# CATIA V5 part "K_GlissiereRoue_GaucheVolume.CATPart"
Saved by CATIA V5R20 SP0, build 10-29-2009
Part number: glissiere_roue_gauche_volume
Publications: "Corps principal", "Corps principal1"
Bounding box of the stored display mesh (mm): x -74.995 to 74.995, y 360 to 515, z -25 to 24.995
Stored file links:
  G:\Khaled_CFAO_2011\ST2M\ST2M_GR1\cdurantin\cdurantin\Khaled\CAD_ThinkMOTION\K_GlissiereRoue_GaucheVolume.CATPart
  C:\Documents and Settings\cdurantin\Bureau\cdurantin\caddy.CATProduct
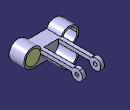
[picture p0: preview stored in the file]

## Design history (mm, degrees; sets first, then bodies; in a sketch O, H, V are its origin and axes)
External parameters (linked from other documents)
  `External.diamètre des barres` = 40 mm
  `External.Surepaisseur du tube` = 10 mm
  `External.largeur de la glissière` = 100 mm
  `External.Ecart entre les barres du corps` = 100 mm
  `External.Longueur de barres du corps` = 800 mm
Set1
  DatumSurface1: linked copy from another document
  Point1: linked copy from another document
  Point2: linked copy from another document
Body1 (main body)
  Sketch1 on face of DatumSurface1, origin (0, 400, 0), H (-1, 0, 0), V (0, 0, 1)
    circle A1 centre (-50, 0) radius 20
    reference projected point E2 (-50, 0) from Point1
    arc A2 centre (-50, 0) radius 25 from (-27.0871, 10) to (-50, -25) ccw
    circle A3 centre (50, 0) radius 20
    reference projected point E4 (50, 0) from Point2
    arc A4 centre (50, 0) radius 25 from (50, -25) to (27.0871, 10) ccw
    line L1 (-27.0871, 10) -> (27.0871, 10)
    reference projected point E5 (-50, 0) from Point1
    line L2 (-50, -25) -> (50, -25)
    reference projected point E6 (-50, 0) from Point1
    radius A1 = 20 {= `External.diamètre des barres` /2}
    radius A2 = 25 {= `External.diamètre des barres` /2+`External.Surepaisseur du tube` /2}
    radius A3 = 20 {= `External.diamètre des barres` /2}
    radius A4 = 25 {= `External.diamètre des barres` /2+`External.Surepaisseur du tube` /2}
    distance L1 E5 = 10 {= `External.Surepaisseur du tube`}
    distance L2 E6 = 25 {= `External.diamètre des barres` /2+`External.Surepaisseur du tube` /2}
    concentricity: E2 A1, A2 A1, E4 A3, A4 A3
    horizontal: L1 H
    tangency: L2 A4
  Pad1: profile Sketch1, direction (0, -1, 0), length 40 {= `External.diamètre des barres`}
  Sketch2 on start face of Pad1, origin (0, 400, 0), H (-1, 0, 0), V (0, 0, 1)
    arc A1 centre (0, 0) radius 20 from (-20, 0) to (20, 0) ccw
    point P1 (0, 0)
    reference projected point E1 (50, 0) from Point2
    reference projected point E2 (-50, 0) from Point1
    arc A2 centre (0, 0) radius 25 from (-25, 0) to (25, 0) ccw
    point P3 (20, 0)
    point P4 (25, 0)
    point P5 (-20, 0)
    point P6 (-25, 0)
    point P7 (-20, 0)
    point P8 (20, 0)
    point P9 (-25, 0)
    point P10 (25, 0)
    line L1 (20, 0) -> (25, 0)
    line L2 (-20, 0) -> (-25, 0)
    distance P1 E1 = 50 {= `External.Ecart entre les barres du corps` /2}
    distance P1 E2 = 50 {= `External.Ecart entre les barres du corps` /2}
    radius A1 = 20 {= `External.diamètre des barres` /2}
    radius A2 = 25 {= `External.diamètre des barres` /2+`External.Surepaisseur du tube` /2}
    concentricity: A2 A1
    coincidence: P3 A1, P3 H, P4 A2, P5 A1, P5 H, P6 A2, P3 P8, P4 P10, P5 P7, P6 P9
    horizontal: L1 H, L2 H
  Pad2: profile Sketch2, direction (0, 1, 0), length 50 {= `External.largeur de la glissière` -`External.diamètre des barres` -`External.Surepaisseur du tube`}
  Plane1: type Offset, RefPlane zx-plane, Offset 500 {= `External.Longueur de barres du corps` /2+`External.largeur de la glissière`}
  Sketch3 on Plane1, origin (0, 500, 0), H (-1, 0, 0), V (0, 0, 1)
    line L1 (-30, 15) -> (-20, 15)
    line L2 (-20, 15) -> (-20, 5)
    line L3 (-20, 5) -> (-30, 5)
    line L4 (-30, 5) -> (-30, 15)
    length L2 = 10 {= `External.Surepaisseur du tube`}
    length L1 = 10 {= `External.Surepaisseur du tube`}
    distance L3 H = 5 {= `External.Surepaisseur du tube` /2}
    distance L2 V = 20 {= `External.diamètre des barres` /2}
    horizontal: L1 H, L3 H
    vertical: L2 V, L4 V
  Shaft1: profile Sketch3, axis Sketch3.H, angle 360
  Sketch4 on start face of Pad1, origin (0, 400, 0), H (-1, 0, 0), V (0, 0, 1)
    line L1 (-20, 10) -> (-30, 10)
    line L2 (-30, 10) -> (-30, 0)
    line L3 (-30, 0) -> (-20, 0)
    line L4 (-20, 0) -> (-20, 10)
    length L4 = 10 {= `External.Surepaisseur du tube`}
    length L1 = 10 {= `External.Surepaisseur du tube`}
    distance L4 V = 20 {= `External.diamètre des barres` /2}
    distance L3 H = 0
    horizontal: L1 H, L3 H
    vertical: L2 V, L4 V
  Pad3: profile Sketch4, direction (0, 1, 0), up to face of Shaft1 from Sketch3.L1
  Mirror1: of Shaft1, about yz-plane
  Sketch5 on start face of Pad1, origin (0, 400, 0), H (-1, 0, 0), V (0, 0, 1)
    line L1 (20, 10) -> (30, 10)
    line L2 (30, 10) -> (30, 0)
    line L3 (30, 0) -> (20, 0)
    line L4 (20, 0) -> (20, 10)
    length L2 = 10 {= `External.Surepaisseur du tube`}
    length L1 = 10 {= `External.Surepaisseur du tube`}
    distance L4 V = 20 {= `External.diamètre des barres` /2}
    distance H L3 = 0
    horizontal: L1 H, L3 H
    vertical: L2 V, L4 V
  Pad4: profile Sketch5, direction (0, 1, 0), up to face of Mirror1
